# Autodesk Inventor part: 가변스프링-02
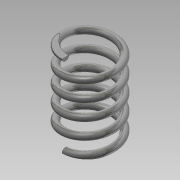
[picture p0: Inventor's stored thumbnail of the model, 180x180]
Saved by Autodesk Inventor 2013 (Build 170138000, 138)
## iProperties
Created: 2014-12
Part Number: 가변스프링-02
Material: 강철, 탄소
Document SubType Name: Modeling
Designer: hanacad19
Density: 7.87 g/cm^3
Mass: 18.8881 g
Surface Area: 32.5247 cm^2
Volume: 2.40001 cm^3
Author: hanacad19
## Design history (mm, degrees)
sketch "스케치1"
  geometry: L1 (0, 0)-(-11, 0); L2 (-11, 0)-(-11, 36.411); L3 (-11, 36.411)-(0, 36.411); L4 (0, 36.411)-(0, 0); C1 r 1.5 at (-11, 0)
  constraints: 8 end point, 2 parallel, 1 centre point, 1 horizontal, 1 perpendicular
  dimensions: "d0" = 3 diameter of C1; "d2" = 22 diameter of L2 L4; "d3" = 36.4112 distance between parallel lines of L1 L3 (derived)
feature "코일1" sketch "스케치1" pitch "d4" = 10; turns "d6" = 5; dims "d5" = 36.4112 (= d3), "d7" = 0, angle "d8" = 90 deg, angle "d9" = 90 deg, "d10" = 0, "d11" = 0
sketch "스케치2"
  geometry: L1 (0, -12.5)-(0, -9.5) reference; 1 further point
  constraints: 1 vertical alignment
extrude "돌출1" cut sketch "스케치2" distance "d12" = 10; taper "d13" = 0 deg
node "작업 평면1"
sketch "스케치3"
  geometry: L1 (0, -9.5)-(0, -12.5) reference; 1 further point
  constraints: 1 vertical alignment
extrude "돌출2" cut sketch "스케치3" distance "d14" = 10; taper "d15" = 0 deg
node "솔리드1"
node "절단 모서리 투영1"
node "절단 모서리 투영2"
